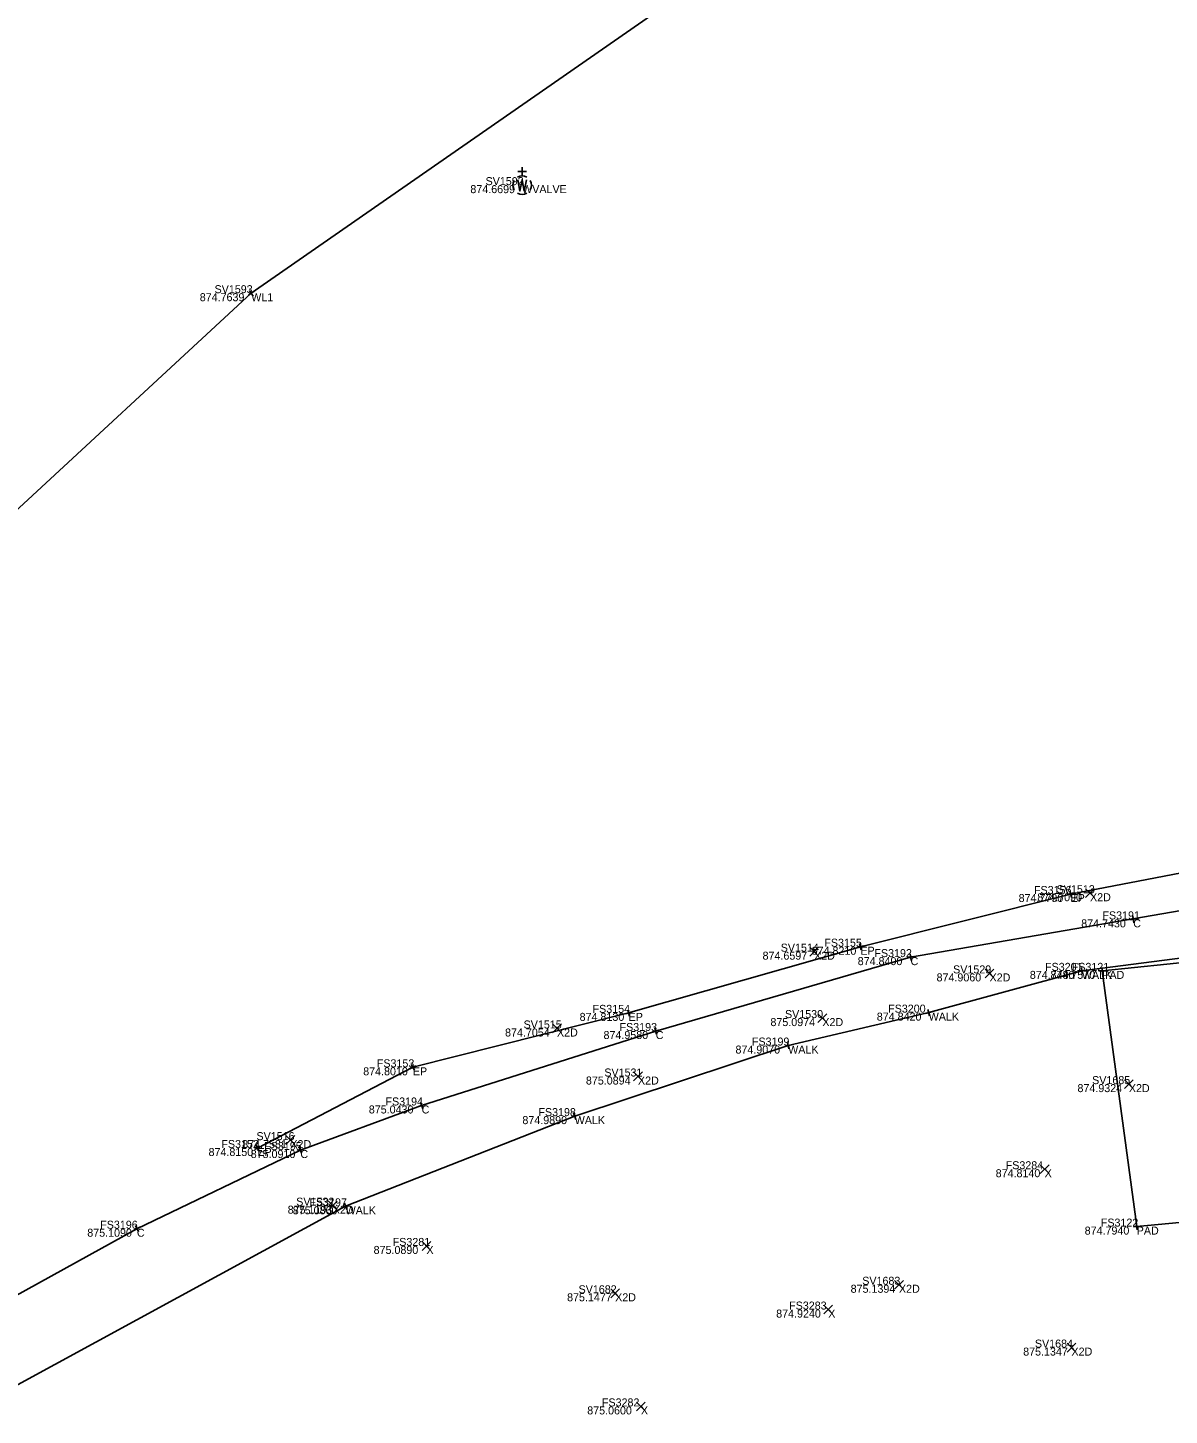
# Model space of a CAD drawing. Extents: x 1479481 to 1575806, y 316056 to 379927.
# Drawn here: x 1480160.91 to 1480169.47, y 379383.47 to 379393.87 of the extents above; entities that cross this region are included whole.
import ezdxf

# ---------------------------------------------------------------- set-up
doc = ezdxf.new("R2010")
doc.units = 0
for name, color, linetype in [('PV_X_Curb', 7, 'Continuous'), ('PV_X_EOP', 7, 'Continuous'), ('RD_X_Concrete_Pad', 7, 'Continuous'), ('SV_X_Random_Point', 7, 'Continuous'), ('SV_X_Shot_Marker', 7, 'Continuous'), ('SV_X_Text_Comment', 7, 'Continuous'), ('SV_X_Text_Elevation', 7, 'Continuous'), ('SV_X_Text_Name', 7, 'Continuous'), ('UT_X_Water', 7, 'Continuous'), ('UT_X_Water_Cells', 7, 'Continuous')]:
    doc.layers.add(name, color=color, linetype=linetype)

msp = doc.modelspace()

# ---------------------------------------------------------------- linework, layer by layer
at = {"layer": 'PV_X_Curb'}
for points in [[(1480180.762, 379386.381), (1480178.806, 379386.86), (1480177.191, 379387.187), (1480175.909, 379387.376), (1480174.182, 379387.527), (1480173.307, 379387.545), (1480172.025, 379387.586), (1480170.646, 379387.439), (1480167.531, 379386.903), (1480165.621, 379386.349), (1480163.867, 379385.791), (1480162.958, 379385.457), (1480161.733, 379384.867), (1480159.898, 379383.853)], [(1480200.436, 379370.31), (1480193.202, 379376.933), (1480192.331, 379377.692), (1480191.145, 379378.864), (1480189.945, 379379.999), (1480188.405, 379381.34), (1480186.948, 379382.631), (1480185.159, 379383.837), (1480183.612, 379384.764), (1480182.42, 379385.277), (1480180.94, 379385.773), (1480179.383, 379386.306), (1480178.708, 379386.55), (1480176.982, 379386.784), (1480175.084, 379387.087), (1480173.11, 379387.257), (1480172.166, 379387.208), (1480170.557, 379387.026), (1480168.815, 379386.8), (1480167.667, 379386.487), (1480166.614, 379386.24), (1480165.014, 379385.711), (1480163.297, 379385.035), (1480160.165, 379383.332)]]:
    msp.add_lwpolyline(points, dxfattribs=at)
at = {"layer": 'PV_X_EOP'}
msp.add_lwpolyline([(1480162.636, 379385.472), (1480163.801, 379386.077), (1480165.418, 379386.485), (1480167.155, 379386.981), (1480168.73, 379387.376), (1480170.459, 379387.707), (1480172.465, 379387.875), (1480174.363, 379387.724), (1480176.285, 379387.6), (1480178.413, 379387.246), (1480180.385, 379386.755), (1480182.516, 379385.858), (1480184.495, 379384.826), (1480186.137, 379383.794), (1480187.578, 379382.895), (1480189.061, 379381.596), (1480190.464, 379380.232), (1480191.921, 379378.963), (1480193.467, 379377.516), (1480195.917, 379375.21)], dxfattribs=at)
at = {"layer": 'RD_X_Concrete_Pad'}
msp.add_lwpolyline([(1480168.968, 379386.8), (1480169.226, 379384.883), (1480173.09, 379385.247), (1480172.844, 379387.2)], close=True, dxfattribs=at)
at = {"layer": 'SV_X_Random_Point'}
for p, q in [((1480168.843, 379387.349), (1480168.909, 379387.415)), ((1480168.843, 379387.415), (1480168.909, 379387.349)), ((1480166.775, 379386.911), (1480166.841, 379386.978)), ((1480166.775, 379386.978), (1480166.841, 379386.911)), ((1480168.09, 379386.747), (1480168.156, 379386.814)), ((1480168.09, 379386.814), (1480168.156, 379386.747)), ((1480166.837, 379386.412), (1480166.903, 379386.479)), ((1480166.837, 379386.479), (1480166.903, 379386.412)), ((1480164.848, 379386.335), (1480164.914, 379386.402)), ((1480164.848, 379386.402), (1480164.914, 379386.335)), ((1480165.455, 379385.975), (1480165.521, 379386.042)), ((1480165.455, 379386.042), (1480165.521, 379385.975)), ((1480169.134, 379385.918), (1480169.2, 379385.984)), ((1480169.134, 379385.984), (1480169.2, 379385.918)), ((1480162.85, 379385.498), (1480162.916, 379385.565)), ((1480162.85, 379385.565), (1480162.916, 379385.498)), ((1480168.503, 379385.28), (1480168.569, 379385.346)), ((1480168.503, 379385.346), (1480168.569, 379385.28)), ((1480163.168, 379385.006), (1480163.234, 379385.073)), ((1480163.168, 379385.073), (1480163.234, 379385.006)), ((1480163.87, 379384.705), (1480163.936, 379384.771)), ((1480163.87, 379384.771), (1480163.936, 379384.705)), ((1480165.284, 379384.349), (1480165.35, 379384.416)), ((1480165.284, 379384.416), (1480165.35, 379384.349)), ((1480167.411, 379384.413), (1480167.477, 379384.48)), ((1480167.411, 379384.48), (1480167.477, 379384.413)), ((1480166.881, 379384.228), (1480166.947, 379384.294)), ((1480166.881, 379384.294), (1480166.947, 379384.228)), ((1480168.704, 379383.942), (1480168.77, 379384.009)), ((1480168.704, 379384.009), (1480168.77, 379383.942)), ((1480165.477, 379383.502), (1480165.543, 379383.568)), ((1480165.477, 379383.568), (1480165.543, 379383.502))]:
    msp.add_line(p, q, dxfattribs=at)
at = {"layer": 'SV_X_Shot_Marker'}
for p, q in [((1480162.611, 379391.894), (1480162.569, 379391.866)), ((1480162.604, 379391.859), (1480162.576, 379391.901)), ((1480162.59, 379391.88), (1480162.59, 379391.88)), ((1480168.706, 379387.37), (1480168.754, 379387.382)), ((1480168.724, 379387.4), (1480168.736, 379387.352)), ((1480168.73, 379387.376), (1480168.73, 379387.376)), ((1480169.204, 379387.161), (1480169.196, 379387.211)), ((1480169.225, 379387.19), (1480169.175, 379387.182)), ((1480169.2, 379387.186), (1480169.2, 379387.186)), ((1480167.131, 379386.974), (1480167.179, 379386.988)), ((1480167.148, 379387.005), (1480167.162, 379386.957)), ((1480167.155, 379386.981), (1480167.155, 379386.981)), ((1480167.556, 379386.907), (1480167.506, 379386.899)), ((1480167.535, 379386.878), (1480167.527, 379386.928)), ((1480167.531, 379386.903), (1480167.531, 379386.903)), ((1480168.839, 379386.803), (1480168.79, 379386.797)), ((1480168.818, 379386.775), (1480168.811, 379386.825)), ((1480168.815, 379386.8), (1480168.815, 379386.8)), ((1480168.993, 379386.803), (1480168.943, 379386.797)), ((1480168.965, 379386.825), (1480168.971, 379386.775)), ((1480168.968, 379386.8), (1480168.968, 379386.8)), ((1480165.394, 379386.479), (1480165.442, 379386.491)), ((1480165.412, 379386.509), (1480165.424, 379386.461)), ((1480165.418, 379386.485), (1480165.418, 379386.485)), ((1480167.691, 379386.494), (1480167.643, 379386.48)), ((1480167.674, 379386.463), (1480167.66, 379386.511)), ((1480167.667, 379386.487), (1480167.667, 379386.487)), ((1480165.628, 379386.325), (1480165.614, 379386.373)), ((1480165.645, 379386.356), (1480165.597, 379386.342)), ((1480165.621, 379386.349), (1480165.621, 379386.349)), ((1480166.62, 379386.216), (1480166.608, 379386.264)), ((1480166.638, 379386.246), (1480166.59, 379386.234)), ((1480166.614, 379386.24), (1480166.614, 379386.24)), ((1480163.779, 379386.065), (1480163.823, 379386.089)), ((1480163.789, 379386.099), (1480163.813, 379386.055)), ((1480163.801, 379386.077), (1480163.801, 379386.077)), ((1480163.891, 379385.799), (1480163.843, 379385.783)), ((1480163.875, 379385.767), (1480163.859, 379385.815)), ((1480163.867, 379385.791), (1480163.867, 379385.791)), ((1480165.038, 379385.719), (1480164.99, 379385.703)), ((1480165.022, 379385.687), (1480165.006, 379385.735)), ((1480165.014, 379385.711), (1480165.014, 379385.711)), ((1480162.614, 379385.46), (1480162.658, 379385.484)), ((1480162.624, 379385.494), (1480162.648, 379385.45)), ((1480162.636, 379385.472), (1480162.636, 379385.472)), ((1480162.981, 379385.466), (1480162.935, 379385.448)), ((1480162.967, 379385.434), (1480162.949, 379385.48)), ((1480162.958, 379385.457), (1480162.958, 379385.457)), ((1480163.32, 379385.044), (1480163.274, 379385.026)), ((1480163.306, 379385.012), (1480163.288, 379385.058)), ((1480163.297, 379385.035), (1480163.297, 379385.035)), ((1480169.223, 379384.908), (1480169.229, 379384.858)), ((1480161.756, 379384.878), (1480161.71, 379384.856)), ((1480161.744, 379384.844), (1480161.722, 379384.89)), ((1480161.733, 379384.867), (1480161.733, 379384.867)), ((1480169.251, 379384.886), (1480169.201, 379384.88)), ((1480169.226, 379384.883), (1480169.226, 379384.883))]:
    msp.add_line(p, q, dxfattribs=at)
at = {"layer": 'UT_X_Water'}
msp.add_lwpolyline([(1480169.204, 379397.823), (1480165.761, 379394.087), (1480162.59, 379391.88), (1480159.156, 379388.706), (1480148.911, 379378.819), (1480120.344, 379350.087), (1480106.297, 379335.736), (1480080.736, 379308.289), (1480073.091, 379299.637), (1480056.748, 379281.628), (1480051.266, 379275.974)], dxfattribs=at)
at = {"layer": 'UT_X_Water_Cells'}
for p, q in [((1480164.62, 379392.76), (1480164.62, 379392.824)), ((1480164.652, 379392.792), (1480164.588, 379392.792)), ((1480164.62, 379392.69), (1480164.62, 379392.69))]:
    msp.add_line(p, q, dxfattribs=at)
msp.add_lwpolyline([(1480164.588, 379392.731), (1480164.604, 379392.645), (1480164.62, 379392.731), (1480164.636, 379392.645), (1480164.652, 379392.731)], dxfattribs=at)
for start, end in [(150.0184, 209.9816), (60.0184, 120.0157), (330.0184, 29.9816), (239.9843, 299.9816)]:
    msp.add_arc((1480164.62, 379392.69), 0.07, start, end, dxfattribs=at)

# ---------------------------------------------------------------- texts
at = {"layer": 'SV_X_Text_Comment'}
for s, p in [('WVALVE', (1480164.62, 379392.63)), ('WL1', (1480162.59, 379391.82)), ('EP', (1480168.73, 379387.316)), ('X2D', (1480168.876, 379387.322)), ('C', (1480169.2, 379387.126)), ('X2D', (1480166.808, 379386.884)), ('EP', (1480167.155, 379386.921)), ('C', (1480167.531, 379386.843)), ('X2D', (1480168.123, 379386.721)), ('WALK', (1480168.815, 379386.74)), ('PAD', (1480168.968, 379386.74)), ('EP', (1480165.418, 379386.425)), ('WALK', (1480167.667, 379386.427)), ('X2D', (1480164.881, 379386.308)), ('X2D', (1480166.87, 379386.386)), ('C', (1480165.621, 379386.289)), ('WALK', (1480166.614, 379386.18)), ('EP', (1480163.801, 379386.017)), ('X2D', (1480165.488, 379385.948)), ('X2D', (1480169.167, 379385.891)), ('C', (1480163.867, 379385.731)), ('WALK', (1480165.014, 379385.651)), ('X2D', (1480162.883, 379385.471)), ('EP', (1480162.636, 379385.412)), ('C', (1480162.958, 379385.397)), ('X', (1480168.536, 379385.253)), ('X2D', (1480163.201, 379384.98)), ('WALK', (1480163.297, 379384.975)), ('C', (1480161.733, 379384.807)), ('PAD', (1480169.226, 379384.823)), ('X', (1480163.903, 379384.678)), ('X2D', (1480167.444, 379384.387)), ('X2D', (1480165.317, 379384.323)), ('X', (1480166.914, 379384.201)), ('X2D', (1480168.737, 379383.916)), ('X', (1480165.51, 379383.475))]:
    msp.add_text(s, height=0.06, dxfattribs=at).set_placement(p)
at = {"layer": 'SV_X_Text_Elevation'}
for s, p in [('874.6699', (1480164.232, 379392.63)), ('874.7639', (1480162.204, 379391.82)), ('874.7790', (1480168.341, 379387.316)), ('874.7090', (1480168.481, 379387.322)), ('874.7430', (1480168.81, 379387.126)), ('874.6597', (1480166.422, 379386.884)), ('874.8210', (1480166.79, 379386.921)), ('874.8400', (1480167.135, 379386.843)), ('874.9060', (1480167.726, 379386.721)), ('874.7480', (1480168.425, 379386.74)), ('874.7570', (1480168.58, 379386.74)), ('874.8130', (1480165.051, 379386.425)), ('874.8420', (1480167.278, 379386.427)), ('874.7054', (1480164.492, 379386.308)), ('875.0974', (1480166.481, 379386.386)), ('874.9580', (1480165.23, 379386.289)), ('874.9070', (1480166.219, 379386.18)), ('874.8010', (1480163.429, 379386.017)), ('875.0894', (1480165.098, 379385.948)), ('874.9324', (1480168.782, 379385.891)), ('875.0430', (1480163.471, 379385.731)), ('874.9890', (1480164.622, 379385.651)), ('874.7581', (1480162.522, 379385.471)), ('874.8150', (1480162.27, 379385.412)), ('875.0910', (1480162.586, 379385.397)), ('874.8140', (1480168.169, 379385.253)), ('875.1193', (1480162.863, 379384.98)), ('875.0860', (1480162.901, 379384.975)), ('875.1090', (1480161.361, 379384.807)), ('874.7940', (1480168.836, 379384.823)), ('875.0890', (1480163.507, 379384.678)), ('875.1394', (1480167.082, 379384.387)), ('875.1477', (1480164.957, 379384.323)), ('874.9240', (1480166.524, 379384.201)), ('875.1347', (1480168.375, 379383.916)), ('875.0600', (1480165.108, 379383.475))]:
    msp.add_text(s, height=0.06, dxfattribs=at).set_placement(p)
at = {"layer": 'SV_X_Text_Name'}
for s, p in [('SV1592', (1480164.346, 379392.69)), ('SV1593', (1480162.315, 379391.88)), ('FS3156', (1480168.456, 379387.376)), ('SV1513', (1480168.626, 379387.382)), ('FS3191', (1480168.969, 379387.186)), ('SV1514', (1480166.558, 379386.944)), ('FS3155', (1480166.885, 379386.981)), ('FS3192', (1480167.26, 379386.903)), ('SV1529', (1480167.85, 379386.781)), ('FS3201', (1480168.539, 379386.8)), ('FS3121', (1480168.739, 379386.8)), ('FS3154', (1480165.148, 379386.485)), ('SV1530', (1480166.59, 379386.446)), ('FS3200', (1480167.363, 379386.487)), ('SV1515', (1480164.631, 379386.368)), ('FS3193', (1480165.35, 379386.349)), ('FS3199', (1480166.342, 379386.24)), ('FS3153', (1480163.531, 379386.077)), ('SV1531', (1480165.236, 379386.008)), ('SV1685', (1480168.892, 379385.951)), ('FS3194', (1480163.596, 379385.791)), ('FS3198', (1480164.742, 379385.711)), ('FS3152', (1480162.366, 379385.472)), ('SV1516', (1480162.629, 379385.531)), ('FS3195', (1480162.687, 379385.457)), ('FS3284', (1480168.244, 379385.313)), ('SV1532', (1480162.927, 379385.04)), ('FS3197', (1480163.026, 379385.035)), ('FS3196', (1480161.458, 379384.867)), ('FS3122', (1480168.957, 379384.883)), ('FS3281', (1480163.65, 379384.738)), ('SV1683', (1480167.169, 379384.447)), ('SV1682', (1480165.043, 379384.383)), ('FS3283', (1480166.621, 379384.261)), ('SV1684', (1480168.463, 379383.976)), ('FS3282', (1480165.218, 379383.535))]:
    msp.add_text(s, height=0.06, dxfattribs=at).set_placement(p)

doc.saveas('drawing.dxf')
